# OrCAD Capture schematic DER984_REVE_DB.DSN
size C
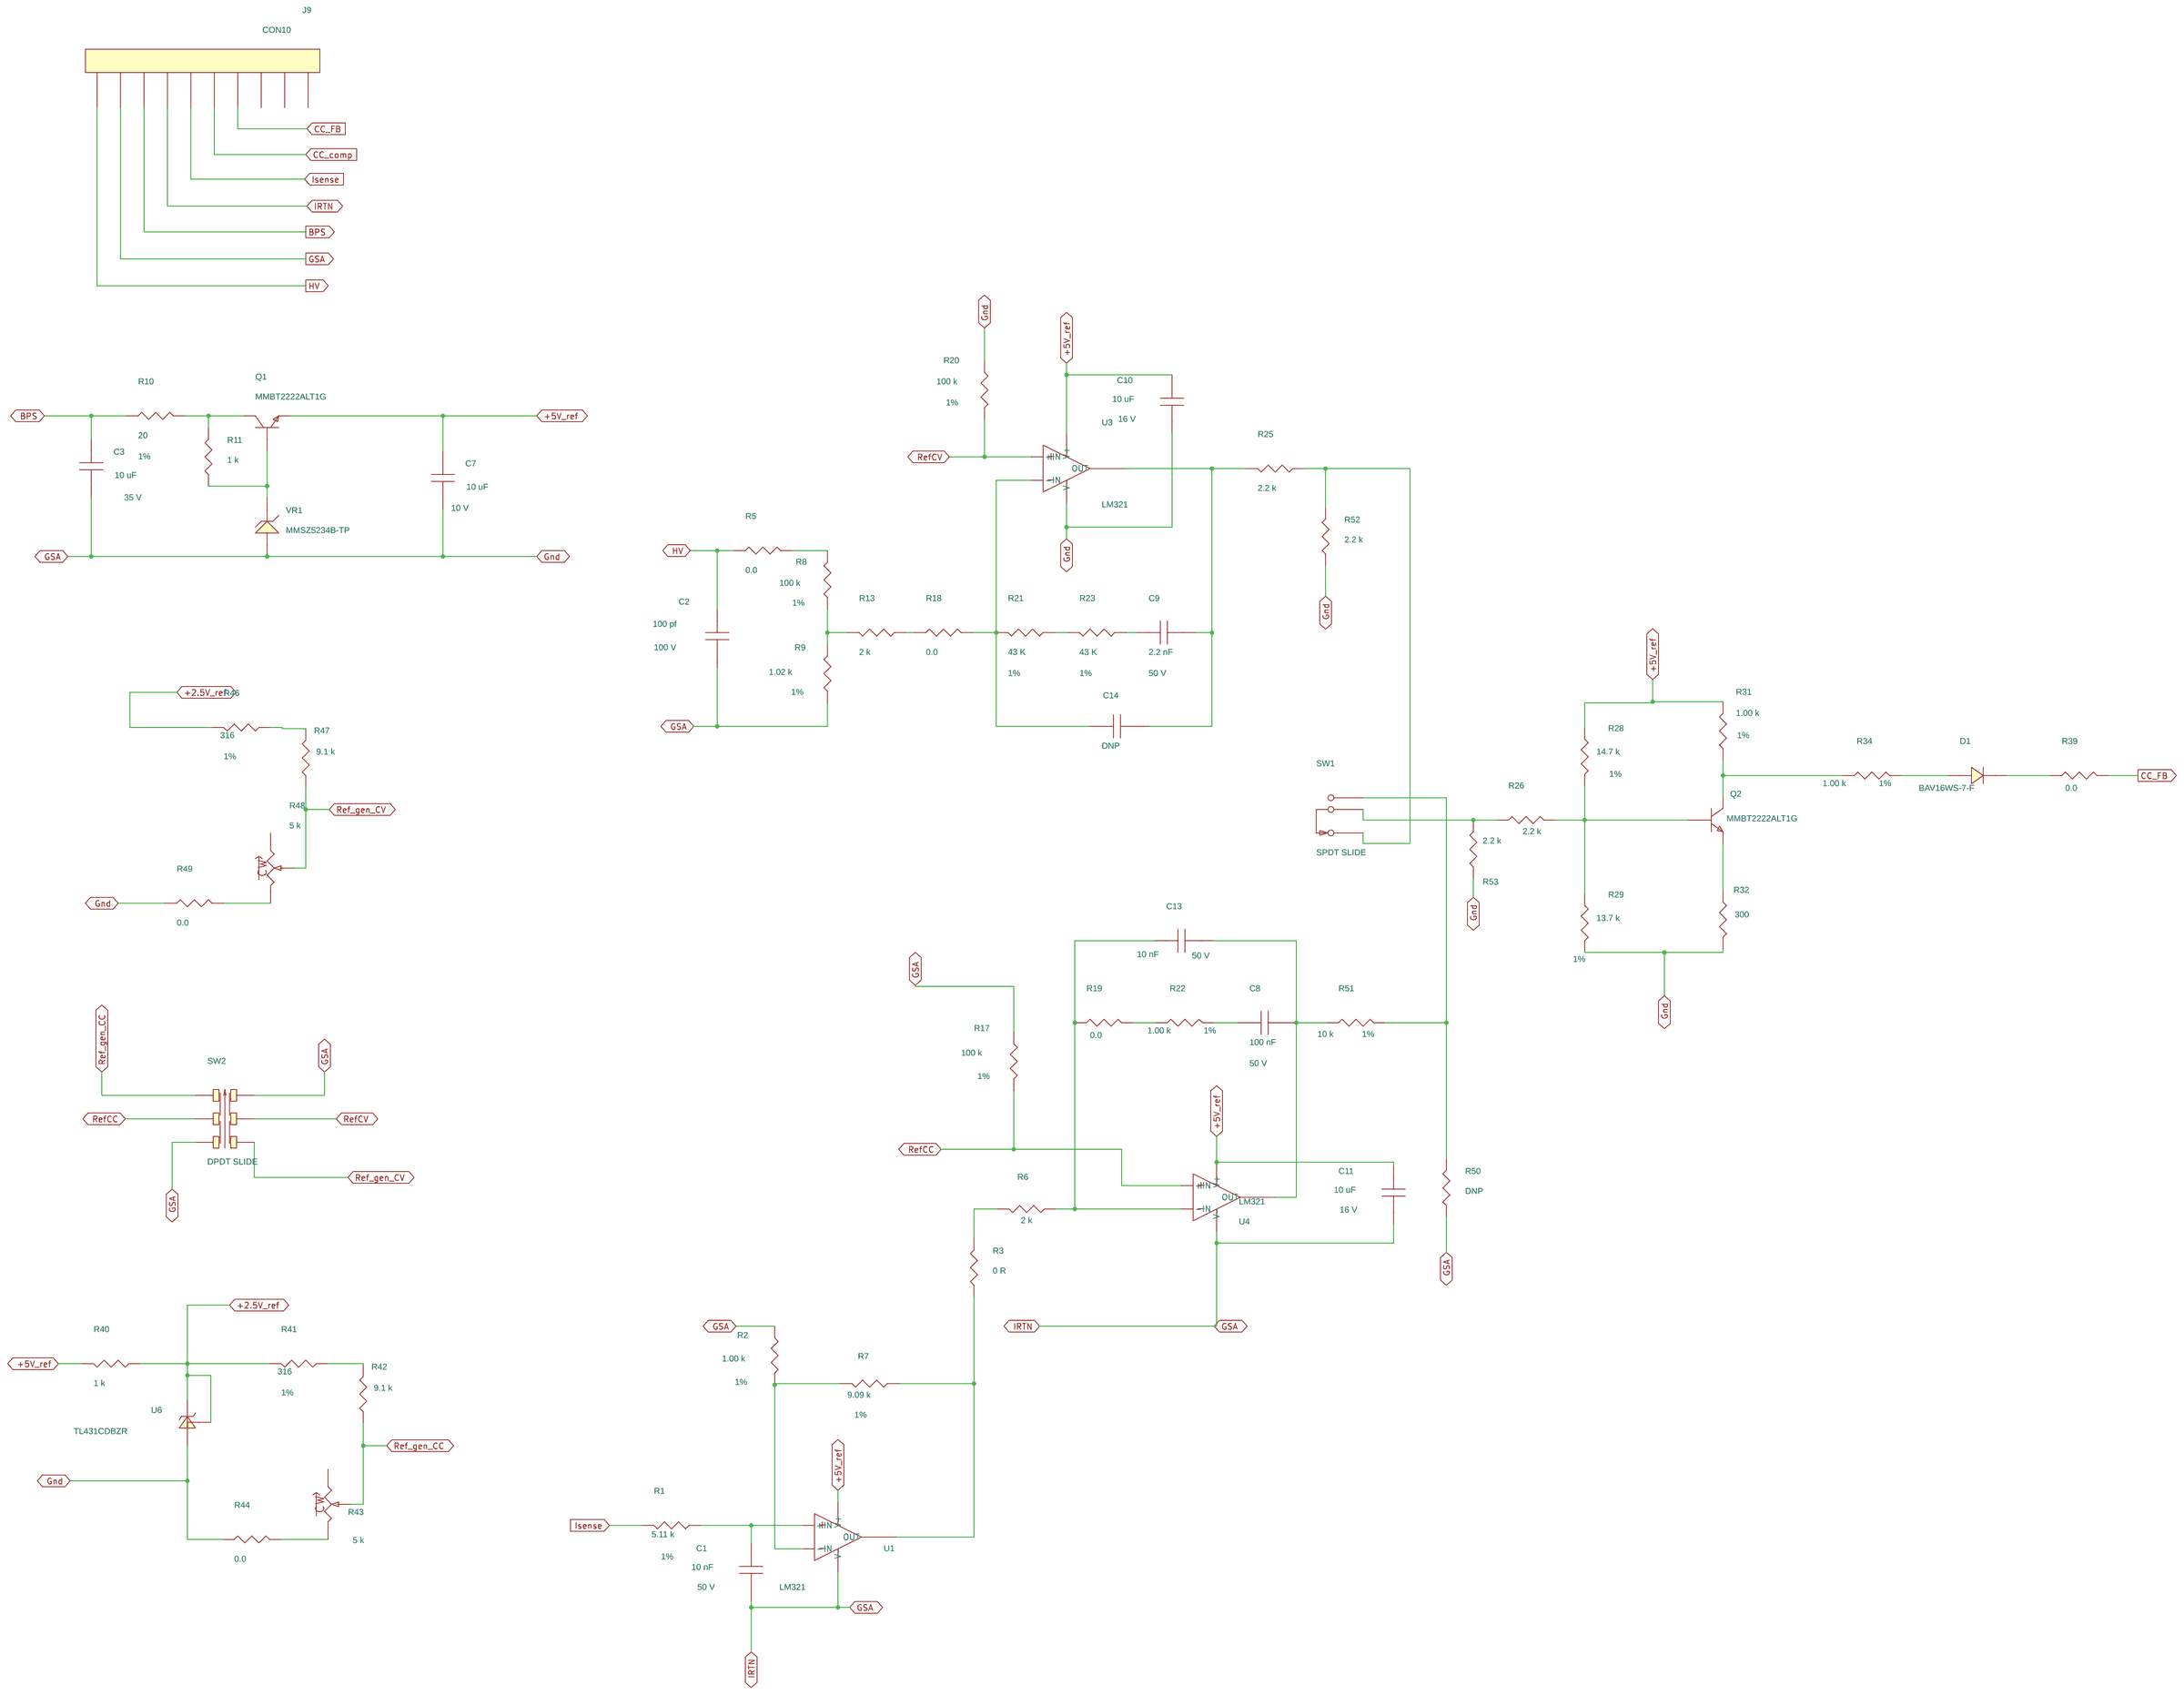
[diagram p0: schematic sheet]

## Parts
C1  10 nF  [pismc0805]
C2  100 pf  [pismc0805]
C3  10 uF  [pismc0805]
C7  10 uF  [pismc0805]
C8  100 nF  [pismc0805]
C9  2.2 nF  [pismc0805]
C10  10 uF  [pismc0805]
C11  10 uF  [pismc0805]
C13  10 nF  [pismc0805]
C14  DNP  [pismc0805]
D1  BAV16WS-7-F  [pismsod323]
J9  CON10  [pi_unshroud_10ra]
Q1  MMBT2222ALT1G  [pismsot23123_1]
Q2  MMBT2222ALT1G  [pismsot23123_1]
R1  5.11 k  [pismr1206]
R2  1.00 k  [pismr0805]
R3  0 R  [pismr1206]
R5  0.0  [pismr0805]
R6  2 k  [pismr0805]
R7  9.09 k  [pismr0805]
R8  100 k  [pismr0805]
R9  1.02 k  [pismr0805]
R10  20  [pismr1206]
R11  1 k  [pismr0805]
R13  2 k  [pismr0805]
R17  100 k  [pismr0805]
R18  0.0  [pismr0805]
R19  0.0  [pismr0805]
R20  100 k  [pismr0805]
R21  43 K  [pismr0805]
R22  1.00 k  [pismr0805]
R23  43 K  [pismr0805]
R25  2.2 k  [pismr0805]
R26  2.2 k  [pismr0805]
R28  14.7 k  [pismr0805]
R29  13.7 k  [pismr0805]
R31  1.00 k  [pismr0805]
R32  300  [pismr0805]
R34  1.00 k  [pismr0805]
R39  0.0  [pismr0805]
R40  1 k  [pismr0805]
R41  316  [pismr0805]
R42  9.1 k  [pismr0805]
R43  5 k  [pivrespv36w_murata_1]
R44  0.0  [pismr0805]
R46  316  [pismr0805]
R47  9.1 k  [pismr0805]
R48  5 k  [pivrespv36w_murata_1]
R49  0.0  [pismr0805]
R50  DNP  [pismr0805]
R51  10 k  [pismr0805]
R52  2.2 k  [pismr0805]
R53  2.2 k  [pismr0805]
SW1  SPDT SLIDE  [pi_switch_spdt_slide_pcbm_1]
SW2  DPDT SLIDE  [pi_switch_dpdt_slide_EG2209]
U1  LM321  [pismsot235]
U3  LM321  [pismsot235]
U4  LM321  [pismsot235]
U6  TL431CDBZR  [pismsot23123_1]
VR1  MMSZ5234B-TP  [pi_sm_sod-123_12]

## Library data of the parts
C1 C13 = CAP_NP: Disp_Voltage: 50 V; Part Number: 20-09227-00; ROOM: 2; Voltage: 50 V
C2 = CAP_NP: Disp_Voltage: 100 V; Part Number: 24-00030-00; Voltage: 100 V
C3 = CAP_NP: ALT_SYMBOLS: pismc0805_1; Disp_Voltage: 35 V; FPLIST: pismc0805,pismc0805_1; Part Number: 20-01692-00; Voltage: 35 V
C7 = CAP_NP: Disp_Voltage: 10 V; Part Number: 20-01694-00; Voltage: 10 V
C8 = CAP_NP: ALT_SYMBOLS: Unisem_RMCF0805UL; Disp_Voltage: 50 V; FPLIST: pismc0805,Unisem_RMCF0805UL; Part Number: 20-00904-00; Voltage: 50 V
C9 = CAP_NP: ALT_SYMBOLS: Unisem_RMCF0805UL; Disp_Voltage: 50 V; FPLIST: pismc0805,Unisem_RMCF0805UL; Part Number: 20-00961-00; Voltage: 50 V
C10 C11 = CAP_NP: Disp_Voltage: 16 V; Part Number: 20-00676-00; ROOM: 2; Voltage: 16 V
C14 = CAP_NP: Disp_Voltage: 50 V; Part Number: 20-00896-00; Voltage: 50 V
D1 = DIODE: Part Number: 15-00850-00
J9 = CON10: Part Number: 35-00385-00
Q1 Q2 = NPN_BEC: Part Number: 55-00121-00
R1 = R: Disp_Tol: 1%; Part Number: 05-00261-00
R2 R22 R31 R34 = R: Disp_Tol: 1%; Part Number: 05-03310-00
R3 = R: Part Number: 05-06493-00
R5 R18 R19 R39 R44 R49 = R: ALT_SYMBOLS: pismr0805_1; FPLIST: pismr0805,pismr0805_1; Part Number: 05-03159-00
R6 R13 = R: Part Number: 05-01526-00
R7 = R: Disp_Tol: 1%; Part Number: 05-03397-00
R8 R17 R20 = R: Disp_Tol: 1%; Part Number: 05-00780-00
R9 = R: Disp_Tol: 1%; Part Number: 05-03311-00
R10 = R: Disp_Tol: 1%; Part Number: 05-06473-00
R11 R40 = R: Part Number: 05-01519-00
R21 R23 = R: Disp_Tol: 1%; Part Number: 05-06424-00
R25 R26 R50 R52 R53 = R: Part Number: 05-01527-00
R28 = R: Disp_Tol: 1%; Part Number: 05-00700-00
R29 = R: Disp_Tol: 1%; Part Number: 05-00697-00
R32 = R: Part Number: 05-01506-00
R41 R46 = R: Disp_Tol: 1%; Part Number: 05-00636-00
R42 R47 = R: Part Number: 05-01542-00
R43 R48 = POT: Part Number: 05-05570-00
R51 = R: ALT_SYMBOLS: Unisem_RMCF0805UL; Disp_Tol: 1%; FPLIST: pismr0805,Unisem_RMCF0805UL; Part Number: 05-00684-00
SW1 = SW_SLIDE-SPDT: Part Number: 66-00111-00
SW2 = SW_SLIDE-DPDT: Part Number: 66-00212-00
U1 U4 = LM321_SOT23-5: Part Number: 45-00049-00; ROOM: 2
U3 = LM321_SOT23-5: Part Number: 45-00049-00
U6 = TL431CDBZR: Part Number: 45-00492-00
VR1 = DIODE_ZENER: Part Number: 15-01751-00

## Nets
+2.5V_ref: R40.1 R41.1 R46.1 U6.1(C) U6.2(VREF)
+5V_ref: C7.1 C10.1 C11.1 Q1.2(EMITTER) R28.1 R31.2 R40.2 U1.5(V+) U3.5(V+) U4.5(V+)
Gnd: C1.2 C2.2 C3.2 C7.2 C10.2 C11.2 J9.2 J9.4 R2.1 R9.1 R17.1 R20.1 R29.2 R32.2 R44.1 R49.1 R50.1 R52.1 R53.1 SW2.1 SW2.6 U1.2(V-) U3.2(V-) U4.2(V-) U6.3(A) VR1.2
BPS: C3.1 J9.3 R10.1
CC_comp: J9.6
CC_FB: J9.7 R39.2
HV: C2.1 J9.1 R5.1
Isense: J9.5 R1.2
Ref_gen_CC: R42.2 R43.2(WIPER) SW2.3
Ref_gen_CV: R47.2 R48.2(WIPER) SW2.4
RefCC: R17.2 SW2.2 U4.1(+IN)
RefCV: R20.2 SW2.5 U3.1(+IN)
N00379: Q1.1(BASE) R11.1 VR1.1
N00417: Q1.3(COLLECTOR) R10.2 R11.2
N01749: C14.1 R18.2 R21.2 U3.3(-IN)
N01999: C9.2 C14.2 R25.2 U3.4(OUT)
N02394: R8.1 R9.2 R13.2
N05104: D1.2 R34.2
N05139: D1.1 R39.1
N05314: Q2.1(BASE) R26.2 R28.2 R29.1
N05328: Q2.2(EMITTER) R32.1
N05332: Q2.3(COLLECTOR) R31.1 R34.1
N05564: R26.1 R53.2 SW1.2
N12614042: C8.2 C13.2 R51.1 U4.4(OUT)
N12614046: C8.1 R22.2
N12615868: C13.1 R6.1 R19.1 U4.3(-IN)
N12617691: R25.1 R52.2 SW1.1
N12617727: R50.2 R51.2 SW1.3
N12619254: R13.1 R18.1
N12620095: R21.1 R23.2
N12620099: C9.1 R23.1
N12620908: R19.2 R22.1
N12623730: C1.1 R1.1 U1.1(+IN)
N12624245: R2.2 R7.2 U1.3(-IN)
N12624261: R3.1 R7.1 U1.4(OUT)
N12625090: R3.2 R6.2
N12627076: R5.2 R8.2
N12646098: R41.2 R42.1
N12647952: R43.1(CCW) R44.2
N12648329: R46.2 R47.1
N12648469: R48.1(CCW) R49.2

Not connected (* = marked no-connect by the designer): J9 8 9 10; R43 3(CW); R48 3(CW)
